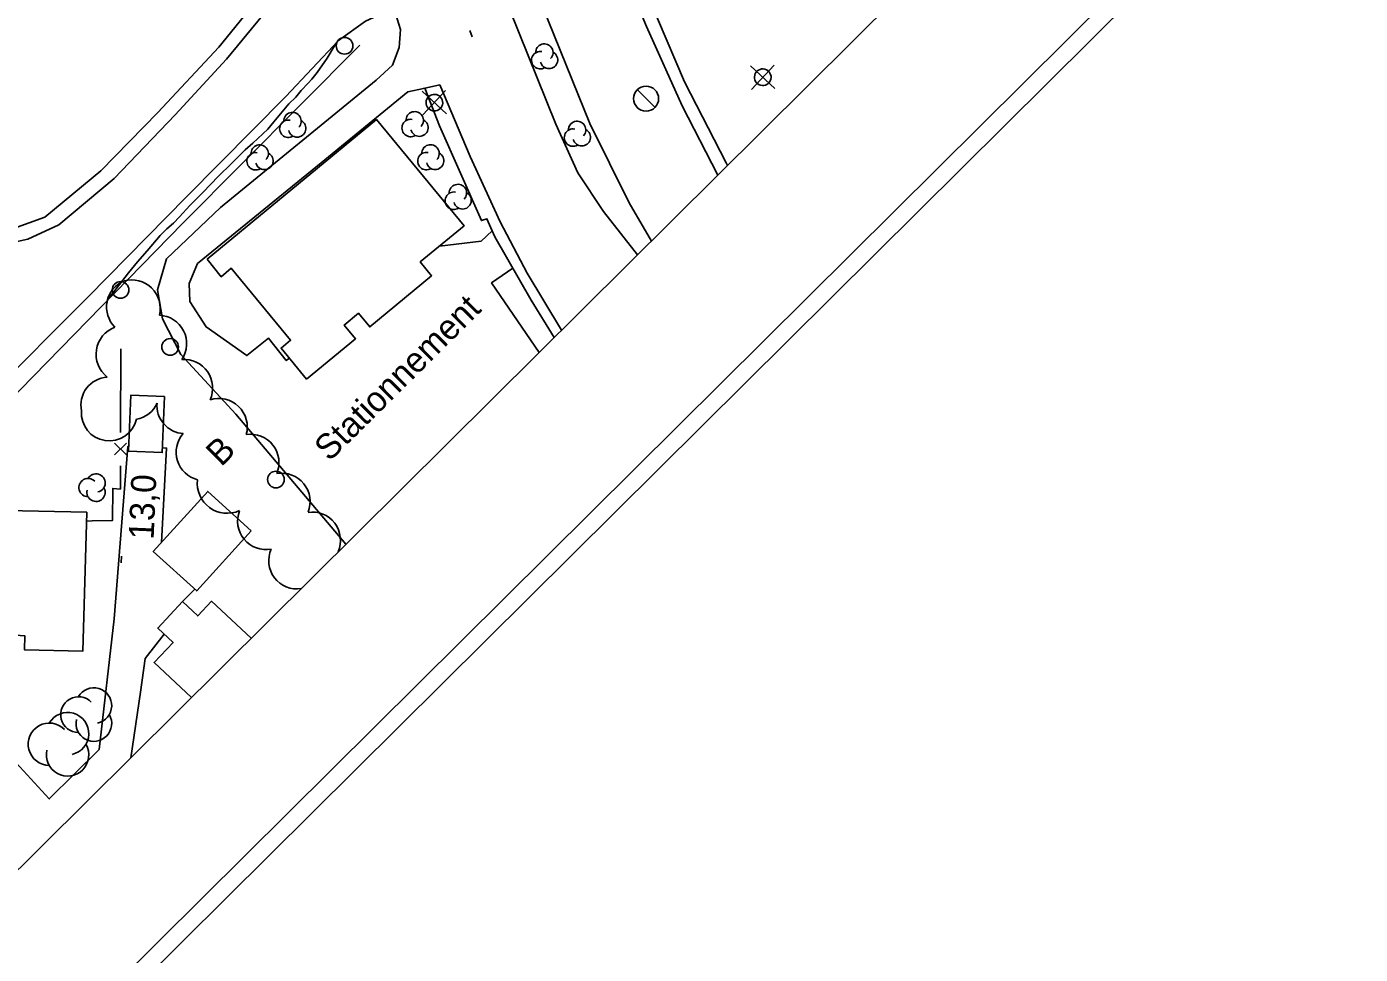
# Model space of a CAD drawing. Extents: x 381879 to 384696, y 5564785 to 5567594.
# Drawn here: x 383850.5 to 384010.5, y 5565863.6 to 5565974.8 of the extents above; entities that cross this region are included whole.
import ezdxf

# ---------------------------------------------------------------- set-up
doc = ezdxf.new("R2010")
doc.units = 0
for name, color, linetype in [('Niveau 19', 7, 'Continuous'), ('Niveau 2', 7, 'Continuous'), ('Niveau 21', 7, 'Continuous'), ('Niveau 22', 7, 'Continuous'), ('Niveau 3', 7, 'Continuous'), ('Niveau 31', 7, 'Continuous'), ('Niveau 36', 7, 'Continuous'), ('Niveau 37', 7, 'Continuous'), ('Niveau 44', 7, 'Continuous'), ('Niveau 52', 7, 'Continuous'), ('Niveau 60', 7, 'Continuous')]:
    doc.layers.add(name, color=color, linetype=linetype)

msp = doc.modelspace()

# ---------------------------------------------------------------- linework, layer by layer
at = {"layer": 'Niveau 19'}
for points in [[(383860.99, 5565903.78), (383862.61, 5565924.45), (383862.73, 5565924.45)], [(383866.76, 5565924.29), (383867.27, 5565924.27), (383866.64, 5565912.94)], [(383860.99, 5565903.78), (383859.16, 5565888.11), (383853.19, 5565882.19), (383841.26, 5565895.17), (383839.12, 5565907.18), (383833.98, 5565911.71), (383832.42, 5565910.19)], [(383869.16, 5565905.86), (383870.65, 5565907.35)], [(383862.97, 5565887.14), (383864.12, 5565894.98), (383864.71, 5565899.05), (383866.99, 5565901.95)]]:
    msp.add_lwpolyline(points, dxfattribs=at)
at = {"layer": 'Niveau 2'}
for points in [[(383884.69, 5565968.5), (383885.32, 5565969.32), (383886.53, 5565971.04), (383887.43, 5565972.51), (383887.56, 5565972.8)], [(383860.15, 5565941.99), (383862.69, 5565945.3), (383863.76, 5565946.61), (383864.94, 5565947.94), (383866.51, 5565949.77), (383867.28, 5565950.55), (383868.08, 5565951.25), (383868.8, 5565951.99), (383870.07, 5565953.36), (383871.62, 5565954.93), (383873.49, 5565956.88), (383875.07, 5565958.42), (383876.69, 5565960.06), (383877.6, 5565960.85), (383879.41, 5565962.51), (383880.14, 5565963.41), (383881.95, 5565965.54), (383882.77, 5565966.35), (383883.43, 5565967.17), (383884.26, 5565968.03), (383884.69, 5565968.5)]]:
    msp.add_lwpolyline(points, dxfattribs=at)
at = {"layer": 'Niveau 21'}
for points in [[(384037.21, 5566060), (384035.77, 5566062.77), (384032.37, 5566069.75), (384030.4, 5566074.29), (384028.68, 5566077.86), (384027.3, 5566079.85), (384025.76, 5566081.01), (384023.87, 5566081.42), (384021.91, 5566081.09), (384019.98, 5566080.3), (384016.38, 5566076.82), (383997.28, 5566057.45), (383977.9, 5566037.71), (383959.91, 5566019.33), (383939.39, 5565998.5), (383924.56, 5565983.35), (383923.59, 5565980.98), (383923.37, 5565979.25), (383923.81, 5565977.3), (383924.84, 5565974.84), (383929.11, 5565965.31), (383933.4, 5565957.01)], [(383908.42, 5565976.93), (383913.98, 5565963.13), (383916.59, 5565957.28), (383919.69, 5565952.64), (383923.76, 5565947.45)], [(383925.43, 5565949.1), (383922.77, 5565953.68), (383918.06, 5565963.22), (383912.38, 5565977.23)], [(383900.06, 5565967.82), (383903.7, 5565959.24), (383907.28, 5565951.41), (383910.54, 5565945.27), (383914.64, 5565938.4)]]:
    msp.add_lwpolyline(points, dxfattribs=at)
at = {"layer": 'Niveau 22'}
for points in [[(383934.58, 5565958.18), (383934.39, 5565958.5), (383929.42, 5565968.18), (383926.15, 5565975.79), (383925.28, 5565978.55), (383925.13, 5565980.29), (383925.64, 5565982.07), (383926.71, 5565983.54), (383931.48, 5565988.58), (383945, 5566002.29)], [(383913.76, 5565937.52), (383911.01, 5565942.02), (383906.64, 5565949.59), (383905.7, 5565951.77), (383905.05, 5565951.56), (383900.03, 5565962.92), (383898.27, 5565967.44)]]:
    msp.add_lwpolyline(points, dxfattribs=at)
at = {"layer": 'Niveau 3'}
for p, q in [((383903.92, 5565973.59), (383903.66, 5565974.34)), ((383861.81, 5565910.51), (383861.87, 5565911.31))]:
    msp.add_line(p, q, dxfattribs=at)
at = {"layer": 'Niveau 31'}
for points in [[(383872.12, 5565946.91), (383892.44, 5565963.68), (383902.96, 5565950.93), (383897.7, 5565946.59), (383899.06, 5565944.94), (383891.64, 5565938.81), (383890.29, 5565940.44), (383888.58, 5565939.03), (383889.94, 5565937.39), (383884.07, 5565932.55), (383881, 5565936.27), (383882.14, 5565937.21), (383875.03, 5565945.83), (383873.83, 5565944.83)], [(383867, 5565930.44), (383866.74, 5565923.73), (383862.71, 5565923.89), (383862.97, 5565930.6)], [(383877.42, 5565914.34), (383870.88, 5565907.14), (383865.67, 5565911.87), (383872.21, 5565919.07)], [(383857.71, 5565916.59), (383857.2, 5565899.91), (383850.22, 5565900.06), (383850.26, 5565901.75), (383848.04, 5565901.9), (383847.15, 5565902.55), (383846.38, 5565903.71), (383845.84, 5565904.89), (383845.74, 5565906.47), (383845.76, 5565910.95), (383844.45, 5565910.94), (383844.51, 5565913.32), (383845.86, 5565913.4), (383846.04, 5565916.84)]]:
    msp.add_lwpolyline(points, close=True, dxfattribs=at)
msp.add_lwpolyline([(383870.25, 5565894.36), (383865.77, 5565898.54), (383868.04, 5565900.97), (383866.2, 5565902.69), (383869.16, 5565905.86), (383871.01, 5565904.14), (383872.66, 5565905.91), (383877.41, 5565901.47)], dxfattribs=at)
at = {"layer": 'Niveau 36'}
for p, q in [((383937.33, 5565970.11), (383940.25, 5565967.39)), ((383937.43, 5565967.29), (383940.15, 5565970.21)), ((383897.93, 5565967.06), (383900.85, 5565964.34)), ((383898.03, 5565964.24), (383900.75, 5565967.16)), ((383925.87, 5565965.12), (383923.75, 5565967.24))]:
    msp.add_line(p, q, dxfattribs=at)
for centre, radius in [((383888.62, 5565972.52), 1), ((383924.8, 5565966.18), 1.5), ((383861.74, 5565943.24), 1), ((383867.69, 5565936.4), 1), ((383880.39, 5565920.5), 1)]:
    msp.add_circle(centre, radius, dxfattribs=at)
for centre in [(383938.8, 5565968.75), (383899.4, 5565965.7)]:
    msp.add_ellipse(centre, major_axis=(0.799, -0.601), ratio=0.999875, dxfattribs=at)
at = {"layer": 'Niveau 37'}
for p, q in [((383861.02, 5565923.45), (383862.44, 5565924.87)), ((383861.03, 5565924.87), (383862.44, 5565923.45))]:
    msp.add_line(p, q, dxfattribs=at)
for points in [[(383890.46, 5565972.6), (383869.2, 5565951.25), (383761.66, 5565841.14)], [(383861.76, 5565936.16), (383861.74, 5565926.16)], [(383861.73, 5565922.16), (383861.72, 5565919.36), (383860.81, 5565919.44), (383860.79, 5565915.6), (383858.34, 5565915.54)], [(383858.34, 5565915.54), (383857.68, 5565915.52)]]:
    msp.add_lwpolyline(points, dxfattribs=at)
at = {"layer": 'Niveau 44'}
for centre, radius, start, end in [((383866.28, 5565936.8), 3.4, 326.0882, 87.9035), ((383862.28, 5565935.53), 3.47, 110.4513, 232.1818), ((383869.36, 5565931.48), 3.43, 335.306, 94.3327), ((383873.53, 5565926.8), 3.42, 344.5759, 107.9398), ((383877.34, 5565922.52), 3.41, 337.2899, 98.7976), ((383857.85, 5565919.53), 1.1, 44.1153, 269.8039), ((383858.8, 5565920.08), 1.1, 282.2692, 149.7262), ((383858.8, 5565918.97), 1.1, 166.9368, 29.6212), ((383856.7, 5565892.31), 2.14, 44.1153, 269.8039), ((383858.54, 5565893.38), 2.14, 282.2692, 149.7262), ((383853.2, 5565888.75), 2.54, 44.1153, 269.8039), ((383855.39, 5565890.02), 2.54, 282.2692, 149.7262), ((383858.54, 5565891.24), 2.14, 166.9368, 29.6212), ((383855.39, 5565887.47), 2.54, 166.9368, 29.6212)]:
    msp.add_arc(centre, radius, start, end, dxfattribs=at)
for centre, major_axis, ratio, start_param, end_param in [((383912.59, 5565971.71), (-0.836, 0.629), 0.999875, 3.020126, 6.959135), ((383912.1, 5565970.79), (-0.836, 0.629), 0.999875, 5.163765, 9.050341), ((383913.15, 5565970.83), (-0.836, 0.629), 0.999875, 0.893509, 4.863384), ((383897.04, 5565963.58), (-0.836, 0.629), 0.999875, 3.020126, 6.959135), ((383881.88, 5565962.57), (-0.836, 0.629), 0.999875, 5.163765, 9.050341), ((383882.37, 5565963.49), (-0.836, 0.629), 0.999875, 3.020126, 6.959135), ((383882.93, 5565962.61), (-0.836, 0.629), 0.999875, 0.893509, 4.863384), ((383896.55, 5565962.66), (-0.836, 0.629), 0.999875, 5.163765, 9.050341), ((383897.6, 5565962.7), (-0.836, 0.629), 0.999875, 0.893509, 4.863384), ((383916.52, 5565962.43), (-0.836, 0.629), 0.999875, 3.020126, 6.959135), ((383916.03, 5565961.51), (-0.836, 0.629), 0.999875, 5.163765, 9.050341), ((383917.08, 5565961.55), (-0.836, 0.629), 0.999875, 0.893509, 4.863384), ((383878.44, 5565959.59), (-0.836, 0.629), 0.999875, 3.020126, 6.959135), ((383898.93, 5565959.61), (-0.836, 0.629), 0.999875, 3.020126, 6.959135), ((383877.95, 5565958.67), (-0.836, 0.629), 0.999875, 5.163765, 9.050341), ((383879, 5565958.71), (-0.836, 0.629), 0.999875, 0.893509, 4.863384), ((383898.44, 5565958.69), (-0.836, 0.629), 0.999875, 5.163765, 9.050341), ((383899.49, 5565958.73), (-0.836, 0.629), 0.999875, 0.893509, 4.863384), ((383902.22, 5565954.86), (-0.836, 0.629), 0.999875, 3.020126, 6.959135), ((383901.73, 5565953.94), (-0.836, 0.629), 0.999875, 5.163765, 9.050341), ((383902.78, 5565953.98), (-0.836, 0.629), 0.999875, 0.893509, 4.863384), ((383863.44, 5565941.18), (-0.95, -3.24), 0.998723, 3.817744, 5.791567), ((383863.12, 5565941.06), (-2.48, 2.32), 0.995392, 3.639153, 5.748762), ((383860.37, 5565929.41), (-1.41, -3.08), 0.999937, 3.636359, 5.346663), ((383863.07, 5565931.06), (2.49, 2.28), 0.999984, 4.146085, 5.118273), ((383869.49, 5565929.37), (2.53, -2.25), 0.994884, 3.780106, 5.372705), ((383860.41, 5565928.51), (2.03, 2.71), 0.989927, 2.146603, 5.117181), ((383871.78, 5565923.76), (0.86, -3.27), 0.996894, 3.724948, 5.789391), ((383874.55, 5565920.05), (-2.18, -2.88), 0.993234, 5.239278, 7.355023), ((383881.08, 5565917.85), (2.65, 2.14), 0.999949, 5.218131, 7.348737), ((383879.2, 5565915.52), (-2.93, -1.76), 0.999827, 5.369748, 7.498474), ((383884.78, 5565913.23), (-0.87, 3.26), 0.993926, 4.024403, 6.182842), ((383882.91, 5565910.74), (3.32, -0.68), 0.991682, 2.910179, 5.062997)]:
    msp.add_ellipse(centre, major_axis=major_axis, ratio=ratio, start_param=start_param, end_param=end_param, dxfattribs=at)
at = {"layer": 'Niveau 52'}
for points in [[(383879.85, 5565994.83), (383881.65, 5565988.77), (383881.85, 5565983.71), (383881.14, 5565979.92), (383878.77, 5565976.15), (383874.44, 5565970.9), (383868.28, 5565964.25), (383860.97, 5565956.62), (383854.33, 5565951.04), (383850.63, 5565949.31), (383844.63, 5565948.02)], [(383848.9, 5565950.61), (383852.66, 5565951.96), (383859.37, 5565957.54), (383866.2, 5565964.5), (383873.53, 5565972.37), (383878.05, 5565977.92), (383879.72, 5565980.57), (383880.35, 5565983.74), (383880.11, 5565988.01), (383878.48, 5565994.53), (383879.85, 5565994.83)], [(383775.19, 5565857.43), (383782.53, 5565864.82), (383793.71, 5565876.94), (383809.73, 5565894.1), (383821.07, 5565905.75), (383830.34, 5565915.06), (383836.74, 5565921.51), (383845.91, 5565930.45), (383857.82, 5565942.38), (383869.66, 5565954.41), (383881.56, 5565966.44), (383887.9, 5565973.16), (383891.13, 5565975.49), (383894.55, 5565977.02)], [(383894.55, 5565977.02), (383895.33, 5565974.46), (383895.17, 5565972.33), (383894.38, 5565970.2), (383892.42, 5565968.4), (383873.72, 5565953.13), (383867.25, 5565946.97), (383866.16, 5565943.27), (383866.78, 5565939.76), (383868.96, 5565935.51), (383875.59, 5565928.32), (383888.79, 5565912.76)], [(383900.06, 5565967.82), (383898.08, 5565967.4), (383896.21, 5565966.99), (383885.8, 5565958.47), (383870.96, 5565946.4), (383869.98, 5565944.03), (383870.06, 5565941.85), (383872.01, 5565938.81), (383876.89, 5565935.37), (383879.51, 5565937.45), (383881.63, 5565934.77), (383882, 5565935.05)], [(383906.32, 5565950.34), (383905, 5565949.08), (383900.02, 5565948.5)], [(383908.81, 5565945.84), (383906.27, 5565944.08), (383911.96, 5565935.74)]]:
    msp.add_lwpolyline(points, dxfattribs=at)
at = {"layer": 'Niveau 60'}
msp.add_lwpolyline([(382780.54, 5564785.16), (381879.11, 5565693.82), (383794.51, 5567593.97), (384695.95, 5566685.3), (382780.55, 5564785.15)], dxfattribs=at)
for points in [[(381881.93, 5565693.86), (383794.53, 5567591.15), (384693.12, 5566685.31), (382780.52, 5564788.02)], [(383653.8, 5566971.92), (383426.67, 5567200.87), (383197.47, 5566973.49), (381907.4, 5565693.71), (382780.65, 5564813.45), (384299.92, 5566320.61)]]:
    msp.add_lwpolyline(points, close=True, dxfattribs=at)

# ---------------------------------------------------------------- texts
at = {"layer": 'Niveau 3'}
msp.add_text('13,0', height=3, rotation=87.5257, dxfattribs=at).set_placement((383865.71, 5565913.26))
at = {"layer": 'Niveau 44'}
msp.add_text('B', height=3, rotation=44.7707, dxfattribs=at).set_placement((383873.82, 5565921.95))
at = {"layer": 'Niveau 52'}
msp.add_text('Stationnement', height=3, rotation=44.7717, dxfattribs=at).set_placement((383886.81, 5565922.57))

doc.saveas('drawing.dxf')
